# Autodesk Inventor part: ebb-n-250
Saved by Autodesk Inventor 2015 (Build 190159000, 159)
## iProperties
Created: 2020-07
Part Number: ebb-n-250
Checked By: TraceParts S.A.
Material: Generic
Catalog Web Link: www.traceparts.com
Document SubType Name: Modeling
Designer: TraceParts
Density: 1 g/cm^3
Appearance: Default
Company: TraceParts S.A.
Author: TraceParts
REFERENCE: EBB-N-250
SUPPLIER: Soler & Palau
DESIGN: EBB-N-250
TraceParts.PartNumber: 10-04022019-080771
TRACEPARTS: TRACEPARTS
TraceParts.PartTitle: EBB-N
TraceParts.InstanceId: 10-04022019-0807717W0EQM1XXDMO68JMMAMYCXC2Y
TraceParts.PartLanguage: en
TraceParts.ClassPath: SOLER_PALAU:10-04022019-080771
TraceParts.PartVersion: 1.0.1
TraceParts.PartStatus: Published
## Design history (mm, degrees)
feature "ebb-n-250"
body "Solid1"
